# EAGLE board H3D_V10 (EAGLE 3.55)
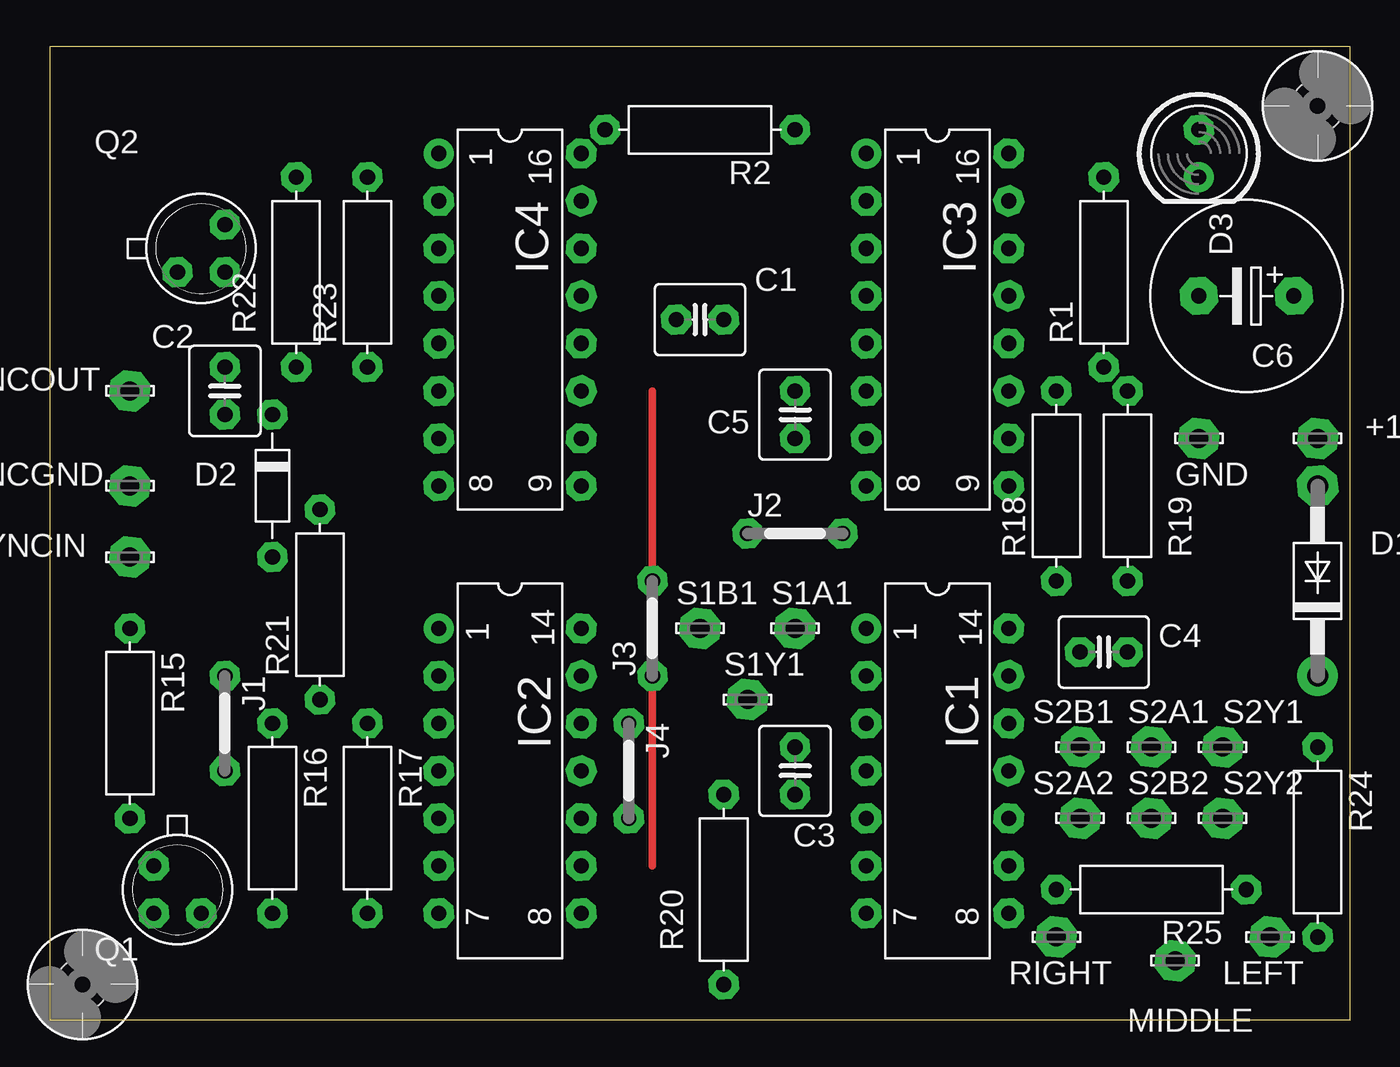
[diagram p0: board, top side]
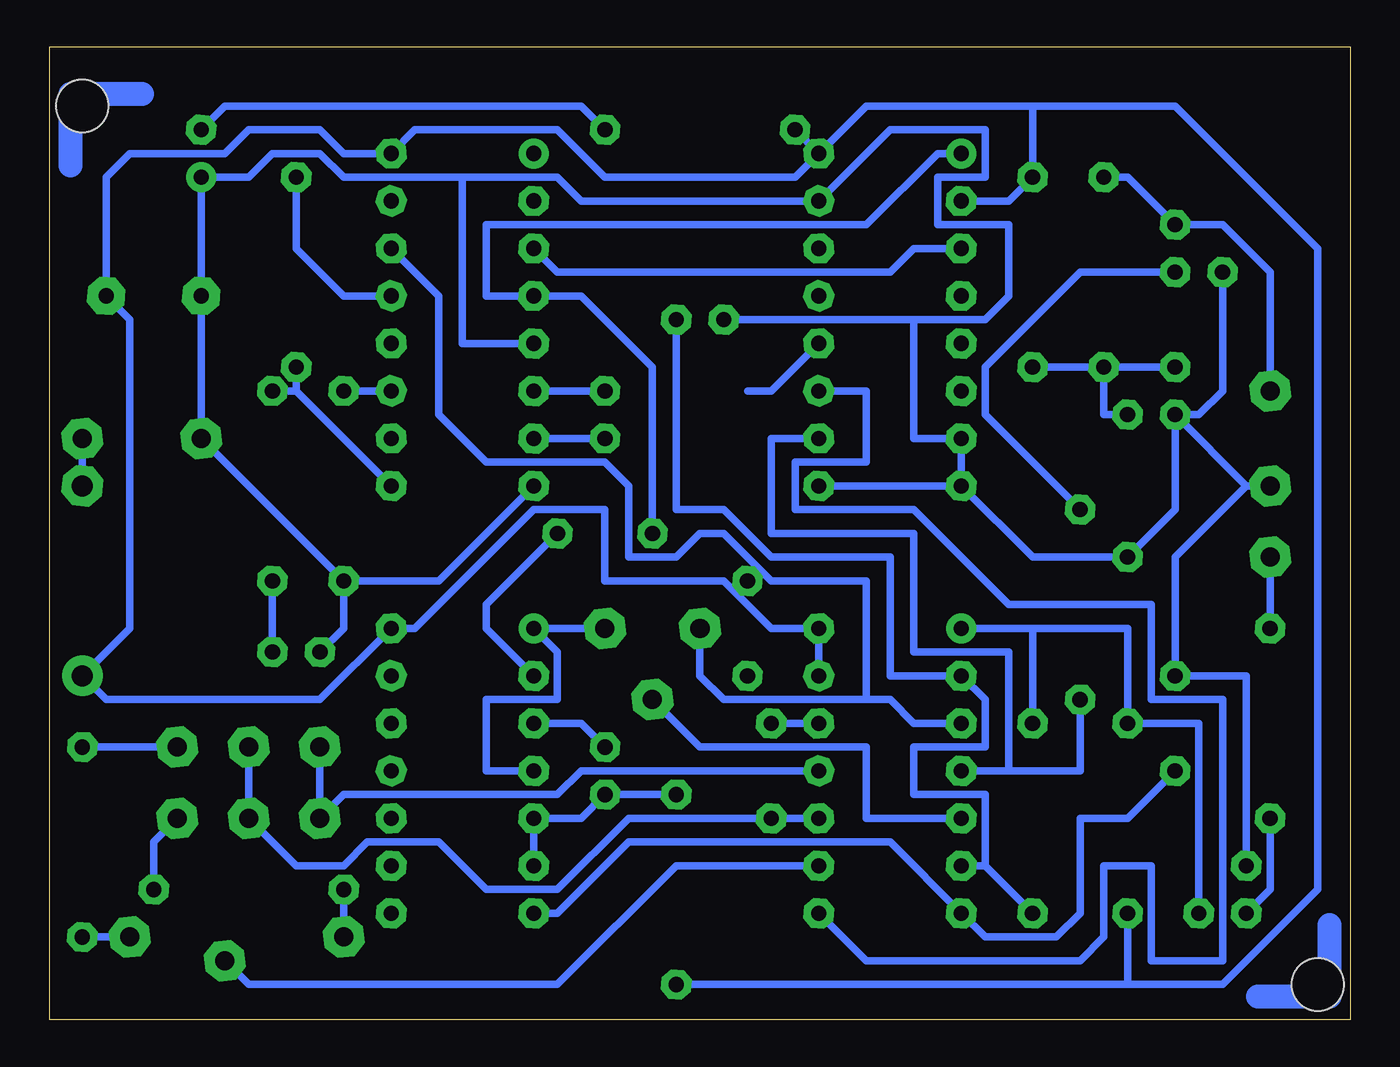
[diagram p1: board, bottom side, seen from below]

Size 69.52 x 52.06 mm. Coordinates in mm from the lower left corner, seen from the top.
Outline: 0,0 69.52,0 69.52,52.06 0,52.06 0,0
Copper layers used: Top, Bottom

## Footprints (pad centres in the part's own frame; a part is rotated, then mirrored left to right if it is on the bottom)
P10 = drill 1.016 pad 2.159 octagon:  0,0
,5-4 = drill 0.813 pad 1.6 octagon:  -1.27,0;  1.27,0
-5 = drill 0.813 pad 2.007 octagon:  -2.54,0;  2.54,0
41-10 = drill 1.118 pad 2.159 octagon:  5.08,0 | drill 1.118 pad 2.159 round:  -5.08,0
7,5 = drill 0.813 pad 1.6 octagon:  -3.81,0;  3.81,0
D5 = drill 0.813 pad 1.6 octagon:  -1.27,0 | drill 0.813 pad 1.6 round:  1.27,0
L14 = drill 0.813 pad 1.6 round:  -7.62,-3.81 | drill 0.813 pad 1.6 octagon:  -5.08,-3.81;  7.62,-3.81;  7.62,3.81;  -2.54,-3.81;  0,-3.81;  5.08,-3.81;  2.54,-3.81;  5.08,3.81;  2.54,3.81;  0,3.81;  -2.54,3.81;  -5.08,3.81;  -7.62,3.81
L16 = drill 0.813 pad 1.6 round:  -8.89,-3.81 | drill 0.813 pad 1.6 octagon:  -6.35,-3.81;  6.35,-3.81;  8.89,-3.81;  -3.81,-3.81;  -1.27,-3.81;  3.81,-3.81;  1.27,-3.81;  8.89,3.81;  6.35,3.81;  3.81,3.81;  1.27,3.81;  -1.27,3.81;  -3.81,3.81;  -6.35,3.81;  -8.89,3.81
L16' = drill 0.813 pad 1.6 round:  -8.89,-3.81 | drill 0.813 pad 1.6 octagon:  -6.35,-3.81;  -3.81,-3.81;  -1.27,-3.81;  1.27,-3.81;  3.81,-3.81;  6.35,-3.81;  8.89,-3.81;  8.89,3.81;  6.35,3.81;  3.81,3.81;  1.27,3.81;  -1.27,3.81;  -3.81,3.81;  -6.35,3.81;  -8.89,3.81
 = drill 0.813 pad 1.6 octagon:  -2.54,0;  2.54,0
18 = drill 0.813 pad 1.6 octagon:  -1.27,-1.27;  1.27,-1.27;  1.27,1.27
10 = drill 0.813 pad 1.6 octagon:  -5.08,0;  5.08,0
2,8 = hole 2.794: 0,0

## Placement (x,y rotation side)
+12V  LSP10  [P10]  67.78,31.11 0 top
C1  100n  [,5-4]  34.76,37.46 0 top
C2  10u  [,5-4]  9.36,33.65 90 top
C3  8.5n  [,5-4]  39.84,13.33 270 top
C4  1u  [,5-4]  56.35,19.68 0 top
C5  30n  [,5-4]  39.84,32.38 90 top
C6  10u  [-5]  63.97,38.73 180 top
D1  1N4004  [41-10]  67.78,23.49 90 top
D2  4.7V  [7,5]  11.9,28.57 90 top
D3  LED gruen  [D5]  61.43,46.35 270 top
GND  LSP10  [P10]  61.43,31.11 0 top
IC1  4001  [L14]  47.46,13.33 270 top
IC2  4030  [L14]  24.6,13.33 270 top
IC3  4046  [L16]  47.46,37.46 270 top
IC4  4520  [L16']  24.6,37.46 270 top
J1  J05  []  9.36,15.87 270 top
J2  J05  []  39.84,26.03 0 top
J3  J25  []  32.22,20.95 90 top
J4  J05  []  30.95,13.33 270 top
LEFT  LSP10  [P10]  65.24,4.44 0 top
MIDDLE  LSP10  [P10]  60.16,3.17 0 top
Q1  2N2222  [18]  6.82,6.98 270 top
Q2  2N2222  [18]  8.09,41.27 0 top
R1  100k  [10]  56.35,40 90 top
R2  2k  [10]  34.76,47.62 180 top
R15  10k  [10]  4.28,15.87 270 top
R16  10k  [10]  11.9,10.79 270 top
R17  100k  [10]  16.98,10.79 270 top
R18  100k  [10]  53.81,28.57 90 top
R19  10k  [10]  57.62,28.57 90 top
R20  10k  [10]  36.03,6.98 270 top
R21  10k  [10]  14.44,22.22 90 top
R22  10k  [10]  13.17,40 270 top
R23  10k  [10]  16.98,40 90 top
R24  470  [10]  67.78,9.52 270 top
R25  470  [10]  58.89,6.98 180 top
RIGHT  LSP10  [P10]  53.81,4.44 0 top
S1A1  LSP10  [P10]  39.84,20.95 0 top
S1B1  LSP10  [P10]  34.76,20.95 0 top
S1Y1  LSP10  [P10]  37.3,17.14 0 top
S2A1  LSP10  [P10]  58.89,14.6 0 top
S2A2  LSP10  [P10]  55.08,10.79 0 top
S2B1  LSP10  [P10]  55.08,14.6 0 top
S2B2  LSP10  [P10]  58.89,10.79 0 top
S2Y1  LSP10  [P10]  62.7,14.6 0 top
S2Y2  LSP10  [P10]  62.7,10.79 0 top
U$2  [2,8]  1.74,1.9 0 top
U$3  [N-W-1]  69.05,50.16 180 top
U$4  [N-W-1]  0.47,0.63 0 top
U$5  [2,8]  67.78,48.89 0 top
VSYNCGND  LSP10  [P10]  4.28,28.57 0 top
VSYNCIN  LSP10  [P10]  4.28,24.76 0 top
VSYNCOUT  LSP10  [P10]  4.28,33.65 0 top

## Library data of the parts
+12V GND LEFT MIDDLE RIGHT S1A1 S1B1 S1Y1 S2A1 S2A2 S2B1 S2B2 S2Y1 S2Y2 VSYNCGND VSYNCIN VSYNCOUT = SOLPAD
C1-C5 = CAP
C6 D2 R1 R2 R15-R25 = DISCRETE
D1 = DIODE
D3 = LED
IC1-IC3 = 40XX
IC4 = 45XX
J1-J4 = JUMPER
Q1 Q2 = NPN
U$2 U$5 = HOLES
U$3 U$4 = MARKS

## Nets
GND: C1. C2. C4. C6. D2. D3. GND. IC1. IC2. IC3. IC4. J1. Q1. Q2. R18. VSYNCGND.
N$1: IC2. Q1. R16. R17.
N$2: Q1. R15.
N$3: IC3. R18.
N$4: IC3. R1.
N$5: R24. S2Y1.
N$6: +12V. D1.
N$7: C5. IC3.
N$8: D3. R2.
N$9: IC2. IC3. S1B1.
N$10: IC2. J4. S2A1. S2B2.
N$11: C3. IC1.
N$12: C3. IC1. R20.
N$13: R15. VSYNCIN.
N$14: IC1. S1A1.
N$15: IC1. IC3. IC4. J2.
N$16: Q2. R21.
N$17: IC3. R1. R19.
N$18: IC3. IC4.
N$19: C5. IC3.
N$20: IC2. IC4. R21.
N$21: Q2. R22. VSYNCOUT.
N$22: C2. D2. R22. R23.
N$23: C1. IC2. R17.
N$24: R25. S2Y2.
N$25: IC2. IC4.
N$26: IC2. S2A2. S2B1.
N$27: IC2. S1Y1.
N$29: C4. R19.
N$30: IC2. IC4. J3. MIDDLE.
N$33: LEFT. R24.
N$34: R25. RIGHT.
VCC: C6. D1. IC1. IC2. IC3. IC4. R2. R16. R20. R23.

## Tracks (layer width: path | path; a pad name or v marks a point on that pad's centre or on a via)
GND
  Top 0.406: 9.36,18.41 J1.
  Bottom 0.406: 28.41,43.81 25.87,46.35 | 5.55,28.57 VSYNCGND. | 5.55,28.57 9.36,32.38 | 9.36,32.38 8.09,32.38 6.82,33.65 6.82,40 | 9.36,32.38 9.36,27.3 11.9,24.76 16.98,24.76 20.79,28.57 | 20.79,28.57 20.79,31.11 23.33,31.11 23.33,37.46 | 5.55,8.25 5.55,18.41 9.36,18.41 9.36,24.76 5.55,28.57 | 23.33,37.46 19.52,37.46 18.25,38.73 18.25,42.54 22.06,42.54 22.06,45.08 19.52,45.08 19.52,47.62 24.6,47.62 28.41,43.81 | 23.33,37.46 33.49,37.46 | 43.65,36.19 47.46,36.19 47.46,45.08 | 47.46,45.08 42.38,45.08 41.11,43.81 28.41,43.81 | 43.65,28.57 48.73,23.49 53.81,23.49 | 53.81,23.49 53.81,20.95 55.08,19.68 | 47.46,45.08 53.81,45.08 55.08,46.35 57.62,46.35 58.89,45.08 D3. C6. GND. 53.81,23.49 | 20.79,28.57 28.41,28.57 | J1. 11.9,10.79 14.44,10.79 14.44,5.71 15.71,4.44 19.52,4.44 20.79,5.71 24.6,9.52 38.57,9.52 42.38,5.71 43.65,5.71
N$1
  Bottom 0.406: 16.98,20.95 20.79,20.95 | 16.98,20.95 16.98,15.87 | 16.98,20.95 11.9,20.95 11.9,15.87 8.09,15.87 Q1.
N$2
  Bottom 0.406: 5.55,5.71 4.28,6.98 R15.
N$3
  Bottom 0.406: 51.27,33.65 R18.
N$4
  Bottom 0.406: 51.27,38.73 53.81,38.73 56.35,41.27 R1.
N$5
  Bottom 0.406: S2Y1. 67.78,14.6
N$6
  Bottom 0.406: 67.78,28.57 +12V.
N$7
  Bottom 0.406: C5. 43.65,33.65
N$8
  Bottom 0.406: 39.84,47.62 41.11,48.89 60.16,48.89 61.43,47.62
N$9
  Bottom 0.406: 20.79,15.87 23.33,15.87 24.6,17.14 25.87,17.14 | 25.87,17.14 33.49,17.14 34.76,18.41 S1B1. | 51.27,41.27 48.73,38.73 48.73,32.38 46.19,29.84 39.84,29.84 38.57,28.57 38.57,24.76 36.03,24.76 34.76,26.03 33.49,26.03 30.95,23.49 25.87,23.49 25.87,17.14
N$10
  Top 0.406: J4. 30.95,15.87
  Bottom 0.406: J4. 28.41,10.79 J4. | J4. 38.57,10.79 42.38,6.98 46.19,6.98 48.73,9.52 52.54,9.52 53.81,8.25 56.35,8.25 S2B2. S2A1. | 30.95,15.87 28.41,15.87
N$11
  Bottom 0.406: 43.65,15.87 41.11,15.87 39.84,14.6
N$12
  Bottom 0.406: 43.65,8.25 43.65,10.79 41.11,10.79 C3. 36.03,12.06
N$13
  Bottom 0.406: 4.28,20.95 VSYNCIN.
N$14
  Bottom 0.406: S1A1. 43.65,20.95 42.38,19.68 42.38,17.14 46.19,17.14 46.19,13.33 43.65,13.33
N$15
  Top 0.406: J2. 37.3,26.03
  Bottom 0.406: 43.65,18.41 46.19,20.95 46.19,22.22 J2. | 37.3,26.03 37.3,34.92 41.11,38.73 43.65,38.73 46.19,38.73 46.19,42.54 25.87,42.54 22.06,46.35 20.79,46.35
N$16
  Bottom 0.406: 9.36,40 14.44,40 19.52,34.92 19.52,32.38 R21.
N$17
  Bottom 0.406: 56.35,33.65 R19. | 51.27,28.57 56.35,33.65 | 56.35,33.65 56.35,34.92
N$18
  Bottom 0.406: 20.79,41.27 23.33,41.27 24.6,40 42.38,40 43.65,41.27
N$19
  Bottom 0.406: 39.84,31.11 43.65,31.11
N$20
  Bottom 0.406: 14.44,17.14 14.44,13.33 18.25,13.33 | 18.25,13.33 20.79,13.33 | 18.25,13.33 18.25,19.68 23.33,19.68 23.33,20.95 23.33,26.03 30.95,26.03 30.95,31.11 28.41,31.11
N$21
  Bottom 0.406: 13.17,45.08 11.9,45.08 Q2. 6.82,42.54 4.28,40 VSYNCOUT.
N$22
  Bottom 0.406: R22. 16.98,34.92 | C2. R22. | R22. 13.17,32.38 D2.
N$23
  Bottom 0.406: C1. 36.03,27.3 33.49,27.3 30.95,24.76 24.6,24.76 24.6,18.41 20.79,18.41 19.52,17.14 19.52,14.6 23.33,14.6 23.33,12.06 19.52,12.06 19.52,8.25 | 19.52,8.25 20.79,8.25 | R17. 19.52,8.25
N$24
  Bottom 0.406: 63.97,6.98 63.97,9.52 S2Y2.
N$25
  Bottom 0.406: 28.41,5.71 25.87,3.17 14.44,3.17 13.17,4.44 13.17,8.25 10.63,8.25 10.63,3.17 6.82,3.17 6.82,17.14 10.63,17.14 10.63,22.22 18.25,22.22 23.33,27.3 29.68,27.3 29.68,29.84 25.87,29.84 25.87,33.65 28.41,33.65
N$26
  Bottom 0.406: 28.41,13.33 41.11,13.33 42.38,12.06 53.81,12.06 S2A2. S2B1.
N$27
  Bottom 0.406: S1Y1. 34.76,14.6 25.87,14.6 25.87,10.79 20.79,10.79
N$29
  Bottom 0.406: C4. 57.62,23.49
N$30
  Top 0.406: 32.22,8.25 32.22,33.65
  Bottom 0.406: 28.41,8.25 32.22,8.25 36.03,8.25 42.38,1.9 58.89,1.9 MIDDLE. | 28.41,36.19 30.95,33.65 32.22,33.65
N$33
  Bottom 0.406: LEFT. R24.
N$34
  Bottom 0.406: RIGHT. R25.
VCC
  Bottom 0.406: 28.41,18.41 IC2. 30.95,20.95 33.49,23.49 39.84,23.49 39.84,27.3 43.65,27.3 50,20.95 IC1. 55.08,17.14 66.51,17.14 D1. 65.24,20.95 65.24,37.46 66.51,38.73 66.51,45.08 65.24,46.35 60.16,46.35 58.89,47.62 55.08,47.62 53.81,46.35 IC3. 50,47.62 42.38,47.62 39.84,45.08 29.68,45.08 IC4. | IC4. 25.87,48.89 16.98,48.89 | 11.9,1.9 R16. | 11.9,1.9 6.82,1.9 1.74,6.98 1.74,41.27 9.36,48.89 16.98,48.89 | 16.98,48.89 R23. 18.25,43.81 20.79,43.81 | 11.9,1.9 R20. | IC4. R2.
